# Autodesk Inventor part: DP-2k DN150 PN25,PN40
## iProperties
Created: 2009-08
Part Number: DP-2k DN150 PN25,PN40
Document SubType Name: Modelowanie
Designer: Marcin Pyzik
Author: Marcin Pyzik
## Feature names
1. Wyciągnięcie proste1 [Extrusion]
2. Faza1 [Chamfer]
3. Bryła wyprowadzona1 [Tagging]
